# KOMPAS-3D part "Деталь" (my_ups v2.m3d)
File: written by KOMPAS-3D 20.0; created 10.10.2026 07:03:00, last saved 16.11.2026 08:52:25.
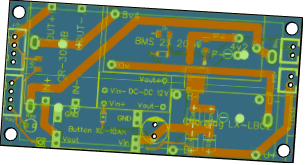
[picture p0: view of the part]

Document properties: Полное имя файла: D:\RicWork\Project-EPS32\box_compas\ups 18650\my_ups v2.m3d

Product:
- Part/product: Деталь
    Масса: 0.0452623

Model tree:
1. Эскиз:1
2. Элемент выдавливания:1
     Расстояние 1 = 1.5
3. Эскиз:2  (with: Элемент выдавливания:1)
4. Элемент выдавливания:2
     Расстояние 2 = 1.5
5. Массив по сетке:1  (with: Элемент выдавливания:2, Эскиз:2)  (4 pattern instances)
     Шаг 1 = 83; Угол раствора = -90; Шаг 2 = 37
6. Эскиз:3  (with: Элемент выдавливания:1)
7. Элемент выдавливания:3
     Расстояние 2 = 1.5
8. Массив по сетке:2  (with: Элемент выдавливания:3, Эскиз:3)  (4 pattern instances)
     Шаг 1 = 10; Угол раствора = -90; Шаг 2 = 2.54
9. Эскиз:4  (with: Элемент выдавливания:1)
10. Элемент выдавливания:4
     Расстояние 2 = 1.5
11. Массив по сетке:3  (with: Элемент выдавливания:4, Эскиз:4)  (2 pattern instances)
     Шаг 1 = 10; Угол раствора = -90; Шаг 2 = 3.5
12. Эскиз:5  (with: Элемент выдавливания:1)
13. Элемент выдавливания:5
     Расстояние 2 = 1.5
14. Массив по сетке:4  (with: Элемент выдавливания:5, Эскиз:5)  (2 pattern instances)
     Шаг 1 = 1; Угол раствора = -90; Шаг 2 = 2.54

Referenced files in D:\myProjects\Progect_esp32\box_compas\ups 18650\: my_ups_pcb v2.png
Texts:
  my_ups_pcb v2.png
